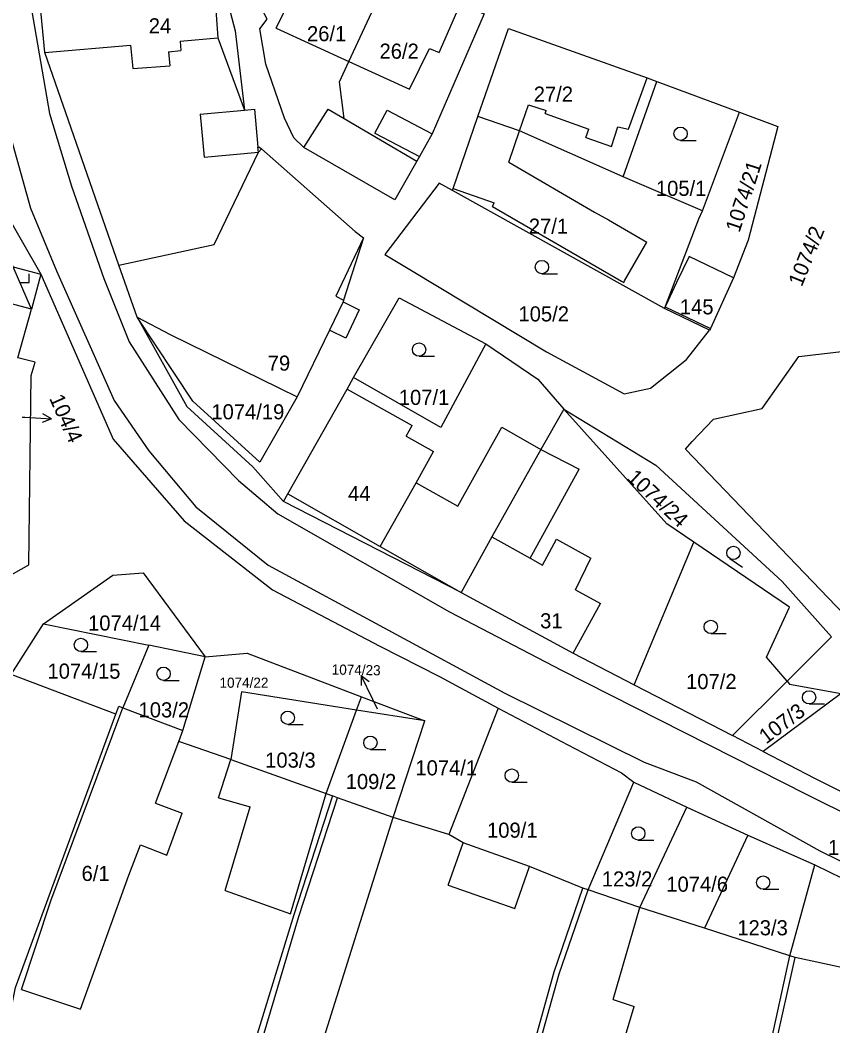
# Model space of a CAD drawing. Extents: x -746176 to -739709, y -1128407 to -1124482.
# Drawn here: x -742325.2 to -742233.7, y -1126165.6 to -1126052.3 of the extents above; entities that cross this region are included whole.
import ezdxf

# ---------------------------------------------------------------- set-up
doc = ezdxf.new("R2010")
doc.units = 0
for name, color, linetype in [('Hranice parcel', 7, 'Continuous'), ('Parcelní čísla', 7, 'Continuous'), ('Pop  PČ popisy', 7, 'Continuous'), ('Vnitřní kresba', 7, 'Continuous'), ('Značky kultur', 7, 'Continuous')]:
    doc.layers.add(name, color=color, linetype=linetype)

msp = doc.modelspace()

# ---------------------------------------------------------------- linework, layer by layer
at = {"layer": 'Hranice parcel'}
for p, q in [((-742257.29, -1126069.93), (-742253.51, -1126059.21)), ((-742253.51, -1126059.21), (-742244.2, -1126062.66)), ((-742248.38, -1126073.76), (-742244.2, -1126062.66)), ((-742244.2, -1126062.66), (-742239.89, -1126064.28)), ((-742248.38, -1126073.76), (-742257.29, -1126069.93)), ((-742252.65, -1126084.79), (-742276.53, -1126071.47)), ((-742252.54, -1126084.5), (-742248.77, -1126074.67)), ((-742248.77, -1126074.67), (-742248.38, -1126073.76)), ((-742314.1, -1126079.89), (-742303.39, -1126077.55)), ((-742312.04, -1126085.73), (-742314.1, -1126079.89)), ((-742322.88, -1126080.92), (-742323.96, -1126084.83)), ((-742244.87, -1126081.3), (-742247.47, -1126087.04)), ((-742251.31, -1126081.83), (-742252.54, -1126084.5)), ((-742325.49, -1126090.34), (-742323.96, -1126084.83)), ((-742247.57, -1126087.2), (-742252.65, -1126084.79)), ((-742247.47, -1126087.04), (-742247.57, -1126087.2)), ((-742263.99, -1126096.11), (-742253.64, -1126102.41)), ((-742275.57, -1126116.75), (-742295.57, -1126106.49)), ((-742256.06, -1126127.14), (-742249.36, -1126111.09)), ((-742326.25, -1126125.97), (-742322.59, -1126120.3)), ((-742322.59, -1126120.3), (-742310.73, -1126122.68)), ((-742233.84, -1126121.75), (-742238.85, -1126126.73)), ((-742310.73, -1126122.68), (-742313.65, -1126129.74)), ((-742304.4, -1126124.01), (-742310.73, -1126122.68)), ((-742306.9, -1126132.3), (-742304.4, -1126124.01)), ((-742238.85, -1126126.73), (-742241.16, -1126124.04)), ((-742314.45, -1126130.46), (-742326.25, -1126125.97)), ((-742245.01, -1126132.86), (-742238.85, -1126126.73)), ((-742238.85, -1126126.73), (-742238.56, -1126127.06)), ((-742300.31, -1126127.94), (-742301.49, -1126135.55)), ((-742287.33, -1126129.99), (-742300.31, -1126127.94)), ((-742256.06, -1126127.14), (-742245.01, -1126132.86)), ((-742287.33, -1126129.99), (-742286.78, -1126128.49)), ((-742286.78, -1126128.49), (-742279.63, -1126131.21)), ((-742313.65, -1126129.74), (-742306.9, -1126132.3)), ((-742290.74, -1126139.38), (-742287.33, -1126129.99)), ((-742279.63, -1126131.21), (-742287.33, -1126129.99)), ((-742271.38, -1126129.77), (-742276.96, -1126144.02)), ((-742283.2, -1126142.1), (-742279.63, -1126131.21)), ((-742241.52, -1126134.66), (-742245.01, -1126132.86)), ((-742301.49, -1126135.55), (-742290.74, -1126139.38)), ((-742261.26, -1126150.24), (-742256.1, -1126138.11)), ((-742256.1, -1126138.11), (-742250.15, -1126140.92)), ((-742290.74, -1126139.38), (-742290.03, -1126139.66)), ((-742255.42, -1126152.21), (-742250.15, -1126140.92)), ((-742250.15, -1126140.92), (-742243.28, -1126144.09)), ((-742276.96, -1126144.02), (-742283.2, -1126142.1)), ((-742243.28, -1126144.09), (-742248.16, -1126154.55)), ((-742243.28, -1126144.09), (-742235.72, -1126147.41)), ((-742238.52, -1126157.67), (-742235.72, -1126147.41)), ((-742235.72, -1126147.41), (-742219.77, -1126155.24)), ((-742261.26, -1126150.24), (-742261.84, -1126150.05)), ((-742255.42, -1126152.21), (-742261.26, -1126150.24)), ((-742248.16, -1126154.55), (-742255.42, -1126152.21)), ((-742238.52, -1126157.67), (-742248.16, -1126154.55))]:
    msp.add_line(p, q, dxfattribs=at)
for points in [[(-742323.01, -1126033.89), (-742307.21, -1126040.31), (-742303.55, -1126045.47), (-742302.63, -1126047.36), (-742301.01, -1126053.5), (-742299.94, -1126062.42)], [(-742293.29, -1126066.63), (-742294.4, -1126065.54), (-742295.46, -1126063.33), (-742297.55, -1126057.25), (-742298.22, -1126053.27), (-742297.41, -1126052.17), (-742301.53, -1126044.31), (-742299.77, -1126041.41), (-742291.99, -1126043.99), (-742283.72, -1126047.27)], [(-742293.29, -1126066.63), (-742290.54, -1126062.33), (-742288.73, -1126063.39), (-742289.27, -1126059.25), (-742288.22, -1126056.95), (-742284.85, -1126049.74), (-742283.92, -1126047.8), (-742283.72, -1126047.27)], [(-742283.72, -1126047.27), (-742272.96, -1126051.59), (-742278.82, -1126065.11), (-742280.26, -1126067.67), (-742280.55, -1126068.19), (-742283.01, -1126072.54), (-742293.29, -1126066.63)], [(-742304.36, -1126048.56), (-742303.36, -1126048.48), (-742302.98, -1126053.8), (-742302.95, -1126054.3), (-742299.94, -1126062.42)], [(-742314.1, -1126079.89), (-742322.45, -1126055.94), (-742323.01, -1126050.01)], [(-742273.66, -1126063.16), (-742270.23, -1126053.23), (-742254.62, -1126058.8), (-742253.51, -1126059.21)], [(-742299.94, -1126062.42), (-742298.84, -1126062.32), (-742298.44, -1126066.59)], [(-742276.53, -1126071.47), (-742276.45, -1126071.24), (-742273.66, -1126063.16)], [(-742257.29, -1126069.93), (-742268.97, -1126064.76), (-742273.66, -1126063.16)], [(-742239.89, -1126064.28), (-742243.22, -1126077.07), (-742244.87, -1126081.3)], [(-742330.17, -1126065.29), (-742327.34, -1126073.19), (-742322.88, -1126080.92)], [(-742323.96, -1126084.83), (-742326, -1126080.07), (-742328.74, -1126073.68), (-742332.05, -1126065.97)], [(-742303.39, -1126077.55), (-742298.39, -1126067.15), (-742298.44, -1126066.59)], [(-742298.44, -1126066.59), (-742298.26, -1126066.59), (-742298.04, -1126066.78), (-742287.48, -1126076.1), (-742286.57, -1126076.81), (-742288.8, -1126083.85), (-742288.85, -1126084.02), (-742287.04, -1126084.92), (-742288.56, -1126088.12), (-742290.4, -1126087.23), (-742294.01, -1126094.72)], [(-742276.53, -1126071.47), (-742278.03, -1126070.66), (-742284.14, -1126078.7), (-742281.13, -1126080.51)], [(-742323.96, -1126084.83), (-742332.33, -1126082.65), (-742338.25, -1126081.12), (-742348.85, -1126077.51)], [(-742244.87, -1126081.3), (-742249.89, -1126078.92), (-742251.31, -1126081.83)], [(-742322.88, -1126080.92), (-742314.75, -1126099.48), (-742306.74, -1126108.67), (-742296.81, -1126116.44), (-742284.71, -1126122.79), (-742278, -1126126.23), (-742271.38, -1126129.77)], [(-742281.13, -1126080.51), (-742265.95, -1126089.64), (-742257.2, -1126094.39), (-742254.21, -1126093.73), (-742250.17, -1126090.53), (-742247.57, -1126087.2)], [(-742287.67, -1126092.56), (-742282.53, -1126083.58), (-742272.79, -1126088.75)], [(-742252.65, -1126084.79), (-742252.57, -1126084.58), (-742252.54, -1126084.5)], [(-742312.04, -1126085.73), (-742308.34, -1126087.69), (-742294.01, -1126094.72)], [(-742312.04, -1126085.73), (-742306.45, -1126095.8), (-742299, -1126102.6), (-742295.57, -1126106.49)], [(-742294.01, -1126094.72), (-742298.22, -1126102.06), (-742305.78, -1126095.19), (-742312.04, -1126085.73)], [(-742272.79, -1126088.75), (-742277.83, -1126098.16), (-742287.67, -1126092.56)], [(-742272.79, -1126088.75), (-742266.9, -1126092.74), (-742263.99, -1126096.11)], [(-742226.91, -1126088.92), (-742220.21, -1126088.74), (-742209.67, -1126089.51), (-742205.42, -1126090.21), (-742203.87, -1126091.46), (-742201.62, -1126095.17), (-742208.44, -1126114.62), (-742212.86, -1126123.04), (-742219.9, -1126132.27), (-742250.27, -1126100.63), (-742249.53, -1126099.74), (-742247.13, -1126097.23), (-742241.64, -1126096.04), (-742237.53, -1126090.17), (-742226.91, -1126088.92)], [(-742330.04, -1126115.93), (-742328.87, -1126116.21), (-742324.26, -1126113.63), (-742323.99, -1126092.3), (-742323.53, -1126090.81), (-742325.49, -1126090.34)], [(-742295.57, -1126106.49), (-742295.08, -1126105.63), (-742288.41, -1126093.86), (-742287.67, -1126092.56)], [(-742263.99, -1126096.11), (-742266.59, -1126100.65), (-742272.09, -1126110.5), (-742275.57, -1126116.75)], [(-742249.36, -1126111.09), (-742252.4, -1126109.03), (-742263.99, -1126096.11)], [(-742253.64, -1126102.41), (-742239.39, -1126115.53), (-742233.84, -1126121.75)], [(-742241.16, -1126124.04), (-742238.58, -1126118.41), (-742249.36, -1126111.09)], [(-742322.59, -1126120.3), (-742314.77, -1126114.82), (-742311.38, -1126114.53), (-742304.4, -1126124.01)], [(-742275.57, -1126116.75), (-742262.95, -1126123.57), (-742256.06, -1126127.14)], [(-742304.4, -1126124.01), (-742299.64, -1126123.59), (-742286.78, -1126128.49)], [(-742238.56, -1126127.06), (-742232.76, -1126128.14), (-742241.52, -1126134.66)], [(-742314.45, -1126130.46), (-742314.12, -1126129.57), (-742313.65, -1126129.74)], [(-742271.38, -1126129.77), (-742263.55, -1126133.89), (-742257.51, -1126137.07), (-742256.1, -1126138.11)], [(-742328.77, -1126175.93), (-742325.75, -1126161.24), (-742314.45, -1126130.46)], [(-742301.49, -1126135.55), (-742307.36, -1126133.52), (-742306.9, -1126132.3)], [(-742241.52, -1126134.66), (-742235.74, -1126137.65), (-742212.93, -1126149.05), (-742177.34, -1126171.16)], [(-742290.03, -1126139.66), (-742294.39, -1126153.07), (-742302.36, -1126178.95), (-742301.38, -1126193.67)], [(-742283.2, -1126142.1), (-742289.47, -1126139.88), (-742290.03, -1126139.66)], [(-742261.84, -1126150.05), (-742267.85, -1126147.6), (-742275.32, -1126144.93), (-742276.96, -1126144.02)], [(-742274.79, -1126214.34), (-742273.54, -1126205.94), (-742273.34, -1126202.32), (-742273.6, -1126202.3), (-742273.12, -1126195.05), (-742269.02, -1126174.69), (-742269.3, -1126174.61), (-742265.06, -1126159.49), (-742261.84, -1126150.05)], [(-742245.81, -1126193.24), (-742245.74, -1126190.69), (-742238.52, -1126157.67)], [(-742229.8, -1126159.63), (-742230.81, -1126159.4), (-742237.95, -1126157.86), (-742238.52, -1126157.67)]]:
    msp.add_lwpolyline(points, dxfattribs=at)
at = {"layer": 'Pop  PČ popisy'}
for p, q in [((-742324.99, -1126097.01), (-742324.7, -1126097.02)), ((-742324.7, -1126097.02), (-742321.7, -1126097.18)), ((-742321.7, -1126097.18), (-742322.73, -1126097.62)), ((-742321.7, -1126097.18), (-742322.68, -1126096.62)), ((-742286.81, -1126126.09), (-742286.82, -1126127.21)), ((-742285.49, -1126128.79), (-742286.81, -1126126.09)), ((-742286.81, -1126126.09), (-742285.92, -1126126.77)), ((-742284.96, -1126129.91), (-742285.49, -1126128.79))]:
    msp.add_line(p, q, dxfattribs=at)
at = {"layer": 'Vnitřní kresba'}
for p, q in [((-742296.38, -1126053.19), (-742293.13, -1126046.42)), ((-742324.08, -1126050.22), (-742321.93, -1126062.83)), ((-742278.04, -1126055.93), (-742276.03, -1126051.39)), ((-742296.38, -1126053.19), (-742288.22, -1126056.95)), ((-742307.2, -1126054.66), (-742302.95, -1126054.3)), ((-742322.45, -1126055.94), (-742312.78, -1126055.13)), ((-742312.78, -1126055.13), (-742312.54, -1126057.76)), ((-742307.2, -1126054.66), (-742307.11, -1126055.73)), ((-742281.38, -1126060.08), (-742279.12, -1126055.5)), ((-742279.12, -1126055.5), (-742278.04, -1126055.93)), ((-742308.51, -1126055.85), (-742307.11, -1126055.73)), ((-742308.51, -1126055.85), (-742308.37, -1126057.45)), ((-742312.54, -1126057.76), (-742308.37, -1126057.45)), ((-742288.22, -1126056.95), (-742281.38, -1126060.08)), ((-742256.7, -1126064.58), (-742254.62, -1126058.8)), ((-742268.97, -1126064.76), (-742267.96, -1126061.83)), ((-742267.96, -1126061.83), (-742265.97, -1126062.48)), ((-742321.93, -1126062.83), (-742319.44, -1126070.99)), ((-742304.95, -1126062.87), (-742299.94, -1126062.42)), ((-742304.95, -1126062.87), (-742304.51, -1126067.72)), ((-742288.73, -1126063.39), (-742280.55, -1126068.19)), ((-742285.27, -1126065.04), (-742283.9, -1126062.43)), ((-742283.9, -1126062.43), (-742278.82, -1126065.11)), ((-742266.08, -1126062.81), (-742265.97, -1126062.48)), ((-742266.08, -1126062.81), (-742261.19, -1126064.58)), ((-742326.67, -1126064.04), (-742324.05, -1126073.49)), ((-742261.51, -1126065.53), (-742261.19, -1126064.58)), ((-742258.63, -1126066.51), (-742257.89, -1126064.32)), ((-742257.89, -1126064.32), (-742256.7, -1126064.58)), ((-742285.27, -1126065.04), (-742280.26, -1126067.67)), ((-742270.19, -1126068.29), (-742268.97, -1126064.76)), ((-742261.51, -1126065.53), (-742258.63, -1126066.51)), ((-742298.39, -1126067.15), (-742298.04, -1126066.78)), ((-742304.51, -1126067.72), (-742298.39, -1126067.15)), ((-742270.19, -1126068.29), (-742260.53, -1126073.92)), ((-742319.44, -1126070.99), (-742315.8, -1126081.39)), ((-742276.45, -1126071.24), (-742271.85, -1126072.87)), ((-742324.05, -1126073.49), (-742321.12, -1126080.53)), ((-742272.03, -1126073.27), (-742271.85, -1126072.87)), ((-742272.03, -1126073.27), (-742257.51, -1126081.69)), ((-742260.53, -1126073.92), (-742258.95, -1126074.79)), ((-742258.95, -1126074.79), (-742254.63, -1126077.29)), ((-742286.57, -1126076.81), (-742289.68, -1126083.4)), ((-742257.14, -1126081.66), (-742254.63, -1126077.29)), ((-742326, -1126080.07), (-742322.88, -1126080.92)), ((-742321.12, -1126080.53), (-742314.64, -1126095.13)), ((-742315.8, -1126081.39), (-742312.95, -1126088.54)), ((-742257.51, -1126081.69), (-742257.24, -1126081.84)), ((-742257.24, -1126081.84), (-742257.14, -1126081.66)), ((-742289.68, -1126083.4), (-742288.8, -1126083.85)), ((-742288.85, -1126084.02), (-742290.4, -1126087.23)), ((-742252.57, -1126084.58), (-742247.47, -1126087.04)), ((-742312.95, -1126088.54), (-742307.34, -1126097.28)), ((-742288.41, -1126093.86), (-742281.08, -1126097.94)), ((-742314.64, -1126095.13), (-742310.74, -1126100.8)), ((-742307.34, -1126097.28), (-742300.63, -1126104.14)), ((-742281.75, -1126099.15), (-742281.08, -1126097.94)), ((-742275.93, -1126107.04), (-742270.96, -1126098.15)), ((-742270.96, -1126098.15), (-742266.59, -1126100.65)), ((-742281.75, -1126099.15), (-742278.67, -1126100.89)), ((-742310.74, -1126100.8), (-742305.42, -1126107.1)), ((-742266.59, -1126100.65), (-742262.26, -1126102.86)), ((-742280.64, -1126104.39), (-742278.67, -1126100.89)), ((-742267.61, -1126112.55), (-742262.26, -1126102.86)), ((-742300.63, -1126104.14), (-742296.2, -1126107.89)), ((-742284.68, -1126111.56), (-742280.64, -1126104.39)), ((-742280.64, -1126104.39), (-742275.93, -1126107.04)), ((-742295.08, -1126105.63), (-742284.68, -1126111.56)), ((-742305.42, -1126107.1), (-742297.3, -1126113.67)), ((-742296.2, -1126107.89), (-742276.88, -1126118.92)), ((-742272.09, -1126110.5), (-742267.8, -1126112.88)), ((-742266.4, -1126113.66), (-742264.83, -1126110.75)), ((-742264.83, -1126110.75), (-742260.96, -1126112.88)), ((-742284.68, -1126111.56), (-742275.57, -1126116.75)), ((-742267.8, -1126112.88), (-742267.61, -1126112.55)), ((-742267.8, -1126112.88), (-742266.4, -1126113.66)), ((-742262.66, -1126116.47), (-742260.96, -1126112.88)), ((-742297.3, -1126113.67), (-742283.82, -1126120.97)), ((-742262.66, -1126116.47), (-742259.87, -1126118.01)), ((-742276.88, -1126118.92), (-742264.25, -1126125.49)), ((-742262.95, -1126123.57), (-742259.87, -1126118.01)), ((-742283.82, -1126120.97), (-742270.64, -1126128.09)), ((-742264.25, -1126125.49), (-742236.63, -1126139.49)), ((-742270.64, -1126128.09), (-742254.96, -1126135.85)), ((-742313.99, -1126130.63), (-742313.65, -1126129.74)), ((-742321.76, -1126151.49), (-742313.99, -1126130.63)), ((-742309.98, -1126140.49), (-742307.36, -1126133.52)), ((-742302.87, -1126139.86), (-742301.49, -1126135.55)), ((-742254.96, -1126135.85), (-742249.1, -1126138.06)), ((-742249.1, -1126138.06), (-742235.14, -1126145.83)), ((-742309.98, -1126140.49), (-742306.99, -1126141.62)), ((-742302.87, -1126139.86), (-742299.31, -1126140.9)), ((-742294.78, -1126152.93), (-742290.74, -1126139.38)), ((-742293.82, -1126153.25), (-742289.47, -1126139.88)), ((-742236.63, -1126139.49), (-742214.05, -1126150.74)), ((-742308.71, -1126146.33), (-742306.99, -1126141.62)), ((-742302.15, -1126150.33), (-742299.31, -1126140.9)), ((-742293.68, -1126175.34), (-742283.2, -1126142.1)), ((-742277.02, -1126149.7), (-742275.32, -1126144.93)), ((-742312.98, -1126148.6), (-742311.68, -1126145.17)), ((-742311.68, -1126145.17), (-742308.71, -1126146.33)), ((-742235.14, -1126145.83), (-742216.99, -1126154.85)), ((-742269.51, -1126152.34), (-742267.85, -1126147.6)), ((-742318.44, -1126163.68), (-742312.98, -1126148.6)), ((-742302.15, -1126150.33), (-742294.78, -1126152.93)), ((-742277.02, -1126149.7), (-742269.51, -1126152.34)), ((-742264.5, -1126159.68), (-742261.26, -1126150.24)), ((-742325.07, -1126161.47), (-742321.76, -1126151.49)), ((-742258.44, -1126162.59), (-742255.42, -1126152.21)), ((-742299.86, -1126173.52), (-742293.82, -1126153.25)), ((-742242.53, -1126178.6), (-742237.95, -1126157.86)), ((-742268.58, -1126174.24), (-742264.5, -1126159.68)), ((-742325.07, -1126161.47), (-742318.44, -1126163.68)), ((-742258.44, -1126162.59), (-742256.05, -1126163.36)), ((-742257.72, -1126168.93), (-742256.05, -1126163.36))]:
    msp.add_line(p, q, dxfattribs=at)
at = {"layer": 'Značky kultur'}
for p, q in [((-742250.84, -1126065.84), (-742249.09, -1126065.84)), ((-742324.21, -1126081.85), (-742324.21, -1126080.85)), ((-742266.46, -1126080.85), (-742264.71, -1126080.85)), ((-742325.21, -1126081.85), (-742324.21, -1126081.85)), ((-742280.3, -1126090.15), (-742278.55, -1126090.15)), ((-742245.31, -1126112.92), (-742243.86, -1126113.9)), ((-742247.44, -1126121.38), (-742245.69, -1126121.38)), ((-742318.38, -1126123.41), (-742316.63, -1126123.41)), ((-742309.07, -1126126.65), (-742307.32, -1126126.65)), ((-742236.37, -1126129.31), (-742234.62, -1126129.31)), ((-742295.09, -1126131.61), (-742293.34, -1126131.61)), ((-742285.78, -1126134.42), (-742284.03, -1126134.42)), ((-742269.86, -1126138.12), (-742268.11, -1126138.12)), ((-742255.6, -1126144.64), (-742253.85, -1126144.64)), ((-742241.54, -1126150.17), (-742239.79, -1126150.17))]:
    msp.add_line(p, q, dxfattribs=at)
for centre in [(-742250.84, -1126065.09), (-742266.46, -1126080.1), (-742280.3, -1126089.4), (-742244.89, -1126112.3), (-742247.44, -1126120.63), (-742318.38, -1126122.66), (-742309.07, -1126125.9), (-742236.37, -1126128.56), (-742295.09, -1126130.86), (-742285.78, -1126133.67), (-742269.86, -1126137.37), (-742255.6, -1126143.89), (-742241.54, -1126149.42)]:
    msp.add_circle(centre, 0.75, dxfattribs=at)

# ---------------------------------------------------------------- texts
at = {"layer": 'Parcelní čísla'}
for s, height, p in [('24', 1.7, (-742310.74, -1126053.79)), ('26/1', 1.7, (-742292.92, -1126054.67)), ('26/2', 1.7, (-742284.75, -1126056.64)), ('27/2', 1.7, (-742267.38, -1126061.48)), ('105/1', 1.7, (-742253.62, -1126072.09)), ('27/1', 1.7, (-742267.93, -1126076.35)), ('145', 1.7, (-742250.92, -1126085.43)), ('105/2', 1.7, (-742269.1, -1126086.23)), ('79', 1.7, (-742297.34, -1126091.77)), ('107/1', 1.7, (-742282.58, -1126095.63)), ('1074/19', 1.7, (-742303.69, -1126097.25)), ('44', 1.7, (-742288.3, -1126106.46)), ('1074/14', 1.7, (-742317.58, -1126121.04)), ('31', 1.7, (-742266.66, -1126120.79)), ('1074/15', 1.7, (-742322.15, -1126126.46)), ('1074/22', 1.139, (-742302.77, -1126127.48)), ('107/2', 1.7, (-742250.22, -1126127.63)), ('103/2', 1.7, (-742311.89, -1126130.82)), ('103/3', 1.7, (-742297.63, -1126136.48)), ('1074/1', 1.7, (-742280.71, -1126137.35)), ('109/2', 1.7, (-742288.56, -1126138.89)), ('109/1', 1.7, (-742272.64, -1126144.37)), ('1080/8', 1.7, (-742234.24, -1126146.32)), ('6/1', 1.7, (-742318.31, -1126149.24)), ('123/2', 1.7, (-742259.71, -1126149.86)), ('1074/6', 1.7, (-742252.45, -1126150.45)), ('123/3', 1.7, (-742244.45, -1126155.36))]:
    msp.add_text(s, height=height, dxfattribs=at).set_placement(p)
for s, height, rotation, p in [('1074/21', 1.7, 72, (-742244.21, -1126076.3)), ('1074/2', 1.7, 68, (-742237.19, -1126082.4)), ('104/4', 1.7, 294, (-742321.98, -1126094.88)), ('1074/24', 1.7, 317, (-742256.99, -1126103.96)), ('1074/23', 1.139, 359, (-742290.14, -1126125.99)), ('107/3', 1.7, 37, (-742241.2, -1126133.88))]:
    msp.add_text(s, height=height, rotation=rotation, dxfattribs=at).set_placement(p)

doc.saveas('drawing.dxf')
